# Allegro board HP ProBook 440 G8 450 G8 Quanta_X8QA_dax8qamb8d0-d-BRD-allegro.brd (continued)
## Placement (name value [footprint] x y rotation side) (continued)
PR9816  *Short_0201  [S0201]  38.33 104.42 180 top
PR9817  20K_1%_2  [R0201]  36.85 106.63 270 top
PR9819  4.7_5%_4  [R0402]  38.53 102.36 0 top
PR9820  *Short_0201  [S0201]  31.29 103.43 270 top
PR9821  10K_1%_2  [R0201]  30.58 103.43 270 top
PR9822  1K_1%_2  [R0201]  37.39 101.52 180 top
PR9823  1K_1%_2  [R0201]  37.39 100.81 180 top
PR9825  22_5%_8  [R0805]  59.38 94.82 0 bottom
PR9826  100K_1%_2  [R0201]  55.95 95.83 0 bottom
PR9827  1M_5%_2  [R0201]  54.91 95.83 0 bottom
PR9828  10K_1%_2  [R0201]  38.33 105.86 180 top
PR9829  *100K_1%_2  [R0201]  38.35 104.04 180 bottom
PR9830  *Short_0201  [S0201]  41.98 100.53 90 bottom
PR9831  *0_5%_2  [R0201]  41.1 100.4 0 bottom
PR9832  *0_5%_2  [R0201]  39.39 99.97 0 bottom
PR9833  *20K_1%_2  [R0201]  33.63 102.77 270 bottom
PR9900  *Short_0201  [S0201]  60.09 101.01 90 top
PR9901  *2.2_5%_6  [R0603]  74.14 105.74 0 bottom
PR9902  *2.2_5%_6  [R0603]  57.22 99.39 90 bottom
PR10200  113K_1%_4  [R0402]  31.19 93.01 90 bottom
PR10201  5.1_5%_6  [R0603]  26.64 89.05 90 top
PR10202  *Short_0805  [S0805]  29.67 79.32 180 top
PR10203  1_5%_6  [R0603]  25.02 87.45 270 bottom
PR10204  *Short_0402  [S0402]  27.02 93.01 270 bottom
PR10205  *10K_1%_2  [R0201]  28.88 93.01 270 bottom
PR10206  *2.2_5%_6  [R0603]  32.18 82.32 90 bottom
PR10207  10K_1%_2  [R0201]  28.27 91.18 90 top
PR10208  *Short_0402  [S0402]  28.01 93.01 270 bottom
PR10209  *Short_0402  [S0402]  24.53 80.06 0 top
PR10210  15K_1%_2  [R0201]  29.61 93.01 90 bottom
PR10211  12K_1%_2  [R0201]  30.35 93.01 90 bottom
PR10212  *100K_1%_4  [R0402]  21.9 63.55 270 top
PR10213  *22_5%_8  [R0805]  28.14 62.56 0 top
PR10214  *1M_4  [R0402]  22.87 65.86 0 top
PR10215  *Short_0805  [S0805]  31.7 81.35 180 top
PR10501  10K_1%_2  [R0201]  70.79 58.34 180 bottom
PR10502  *Short_0603  [S0603]  57.92 60.12 0 bottom
PR10503  *Short_0402  [S0402]  70.79 59.56 270 bottom
PR10504  22_5%_8  [R0805]  56.26 57.72 90 bottom
PR10505  *Short_0201  [S0201]  61.42 57.41 90 bottom
PR10506  *Short_0201  [S0201]  65.5 61.08 270 bottom
PR10507  100K_1%_2  [R0201]  50.24 57.1 90 bottom
PR10508  *0_5%_2  [R0201]  66.24 61.08 270 bottom
PR10509  1M_1%_2  [R0201]  50.11 58.24 90 bottom
PR10510  6.65K_1%_4  [R0402]  73.55 57.58 180 bottom
PR10511  10K_1%_2  [R0201]  69.42 56.38 0 bottom
PR10512  *Short_0603  [S0603]  90.5 70.18 90 top
PR10514  *Short_0603  [S0603]  84.86 71.32 0 top
PR10515  *Short_0603  [S0603]  84.98 77.7 180 top
PR10516  *Short_0201  [S0201]  92.05 77.37 90 top
PR10517  *Short_0201  [S0201]  91.76 71.63 180 top
PR10518  100K_1%_2  [R0201]  71.91 99.31 180 top
PR10519  22_5%_8  [R0805]  69.34 97.13 0 top
PR10520  1M_1%_2  [R0201]  71.68 98.45 270 top
PR10611  *Short_0603  [S0603]  136.04 92.61 180 top
PR10612  *Short_0201  [S0201]  135.19 97.64 90 top
PR10613  *0_5%_2  [R0201]  134.92 93.72 180 top
PR10614  *Short_0201  [S0201]  134.92 94.46 180 top
PR10615  *Short_0603  [S0603]  136.25 96.57 90 top
PR10617  100K_1%_4  [R0402]  158.82 82.01 0 bottom
PR10618  100K_1%_4  [R0402]  157 76.17 270 bottom
PR10619  100K_1%_2  [R0201]  158.58 77.03 0 bottom
PR10621  *Short_0201  [S0201]  158.32 76.25 180 bottom
PR10622  *Short_0201  [S0201]  157.91 75.31 90 bottom
PR10623  *0_5%_2  [R0201]  134.95 99.39 90 bottom
PR10625  10K_1%_2  [R0201]  119.63 13.33 270 bottom
PU8100  AS393MTR-G1  [SOIC8-6-1_27-24AA02]  39.96 15.53 270 bottom
PU8101  G1363U61U  [DFN6-1_6X1_6-5-7P-0_6H]  177.85 14.12 0 top
PU8102  MC74VHC1G08DFT2G  [SOT353-2_1-65-5P]  188.64 12.32 180 bottom
PU8200  BQ24780SRUYR  [QFN28-4X4-4-29P-BQ24780RUYR]  57.48 6.3 180 top
PU8201  G753T11U  [SOT23-5-2_8-95-5P-G708]  61.92 3.76 180 bottom
PU8601  SYV127FTMC  [QFN13-4X3-45]  167.28 13.46 0 bottom
PU8602  NB680AGD-Z  [QFN12-2X3-5]  142.45 16.13 90 bottom
PU8700  RT8231BGQW  [QFN20-3X3-4-21P-RT6543B]  104.33 11.52 0 top
PU8701  G2822CTB1U  [SOT23-2_8-95-6P-G2822C]  180.82 16.61 0 bottom
PU8800  ISL95860HRTZ-T  [QFN32-4X4-4-33P-ISL95860]  85.27 106.93 0 top
PU8900  SIC536CD-T1-GE3  [POWER-4_5X3_5-5-13P]  94.26 106.1 0 bottom
PU8901  SIC536CD-T1-GE3  [POWER-4_5X3_5-5-13P]  106.54 106.45 0 bottom
PU9100  MP2941BGL-Z  [QFN19-4X3-4]  115.14 106.88 0 bottom
PU9200  NB691GG-Z  [QFN11-2X2-5]  122.14 15.57 90 bottom
PU9500  G2898  [DFN14-3X2-4-11P]  156.31 11.43 180 top
PU9501  G2898  [DFN14-3X2-4-11P]  25.12 11.19 0 top
PU9502  G2898  [DFN14-3X2-4-11P]  175.99 68.46 0 top
PU9600  *74LVC1G32GW  [SOT353-2_1-65-5P-1_1H]  145.13 94.38 270 bottom
PU9601  *74LVC1G32GW  [SOT353-2_1-65-5P-1_1H]  148.74 103.07 180 top
PU9800  MP2988GQ  [QFN20-3X3-4-21P-MP2988]  35.08 103.5 180 top
PU9900  MP86948GQVT-Z  [QFN21-5X3-4-15P]  75.79 108.66 180 bottom
PU9901  MP86948GQVT-Z  [QFN21-5X3-4-15P]  54.3 101.29 270 bottom
PU10200  AOZ2264QI-20  [QFN23-4X4-5-20P]  29 88.39 0 bottom
PU10500  G2822CTB1U  [SOT23-2_8-95-6P-G2822C]  67.79 58.34 180 bottom
PU10501  G2894  [DFN14-3X2-4-11P]  88.16 73.86 90 top
PU10601  G2894  [DFN14-3X2-4-11P]  132.69 94.97 90 top
PU10602  *74LVC1G32GW  [SOT353-2_1-65-5P-1_1H]  145.01 97.69 0 top
PU10603  *74LVC1G32GW  [SOT353-2_1-65-5P-1_1H]  163.09 87.8 0 top
PU10604  *74LVC1G32GW  [SOT353-2_1-65-5P-1_1H]  144.93 103.07 180 top
PU10605  *74LVC1G32GW  [SOT353-2_1-65-5P-1_1H]  160.18 85.89 90 top
PU10606  *74LVC1G32GW  [SOT353-2_1-65-5P-1_1H]  125.7 105.46 270 top
Q500  2N7002K  [SOT23-2-95-3P]  91.13 67.66 0 bottom
Q501  METR3904-G  [SOT23-2-95-3P]  94.59 68.86 270 bottom
Q800  PJE138K  [SOT23-1_38-5-3P]  157.07 51.51 180 top
Q801  PJE138K  [SOT23-1_38-5-3P]  158.33 49.27 180 top
Q1000  *PJE138K  [SOT23-1_38-5-3P]  91.67 64.59 270 bottom
Q1100  2N7002KDW  [SOT363-2_1-65-6P]  152.37 76.92 180 bottom
Q1400  2N7002K  [SOT23-2-95-3P]  159.02 63.8 0 top
Q1500  2N7002K  [SOT23-2-95-3P]  148.94 46.43 270 top
Q1501  BSS84  [SOT23-2-95-3P]  154.9 39.89 270 top
Q1502  BSS84  [SOT23-2-95-3P]  153.89 43.8 0 top
Q3403  PJE138K  [SOT23-1_38-5-3P]  23.95 47.44 180 top
Q3404  PJE138K  [SOT23-1_38-5-3P]  21.26 48.16 180 top
Q3405  PJE138K  [SOT23-1_38-5-3P]  35.4 34.52 180 top
Q3406  PJE138K  [SOT23-1_38-5-3P]  28.62 23.8 0 top
Q3600  *METR3904-G  [SOT23-2-95-3P]  184.55 45.93 180 top
Q4104  2N7002K  [SOT23-2-95-3P]  183.49 68.35 270 top
Q4106  2N7002K  [SOT23-2-95-3P]  184.91 86.28 180 top
Q4108  METR3904-G  [SOT23-2-95-3P]  192.02 69.85 270 top
Q4111  METR3904-G  [SOT23-2-95-3P]  195.86 69.39 0 top
Q4112  *2N7002K  [SOT23-2-95-3P]  188.49 68.84 90 top
Q4200  2N7002K  [SOT23-2-95-3P]  197.1 7.72 90 top
Q4300  *PJE138K  [SOT23-2-95-3P]  18.36 51.74 270 top
Q4400  2N7002KDW  [SOT363-2_1-65-6P]  187.47 33.27 180 top
Q4401  *PJE138K  [SOT23-1_38-5-3P]  146.2 50.62 180 top
Q4703  2N7002KDW  [SOT363-2_1-65-6P]  186.74 9.37 180 top
Q4800  2N7002K  [SOT23-2-95-3P]  202.79 12.19 0 bottom
Q5000  *2N7002KDW  [SOT363-2_1-65-6P]  179.19 62.15 270 top
Q5001  PJE138K  [SOT23-1_38-5-3P]  170.51 32.2 180 top
Q5004  PJE138K  [SOT23-1_38-5-3P]  169.62 34.41 0 top
Q5005  AO3409  [SOT23-2_38-95-3P]  46.14 9.7 180 bottom
Q5006  2N7002K  [SOT23-2-95-3P]  45.88 13.35 180 bottom
Q5101  *DMN2990UDJ-7  [SOT963-1-35-6P-SMT]  168.48 66.11 90 top
Q5201  *PJE138K  [SOT23-1_38-5-3P]  26.69 5.66 0 top
Q5202  *PJE138K  [SOT23-1_38-5-3P]  35.56 9.57 90 top
Q5401  2N7002KDW  [SOT363-2_1-65-6P]  35.33 57.45 180 bottom
Q5403  METR3904-G  [SOT23-2-95-3P]  73.33 45.74 90 top
Q5404  2N7002KDW  [SOT363-2_1-65-6P]  90.66 70.65 0 bottom
Q6100  *PJA138K  [SOT23-2-95-3P]  196.9 69.21 0 bottom
Q6600  LTC044EUBFS8TL  [SOT23-1_7-65-3P]  83.01 64.87 180 bottom
Q6601  LTC044EUBFS8TL  [SOT23-1_7-65-3P]  82.57 62.25 180 bottom
Q6800  METR3904-G  [SOT23-2-95-3P]  46.33 57.94 270 bottom
Q6801  LTC044EUBFS8TL  [SOT23-1_7-65-3P]  59.36 92.4 0 bottom
Q6802  *METR3904-G  [SOT23-2-95-3P]  39.77 58.27 180 bottom
Q6900  PJT138K  [SOT363-2_1-65-6P-PJ4N3KDW]  77.41 94.54 180 bottom
Q6901  DMN5L06DWK-7  [SOT363-2_1-65-6P-DMC2004DWK-7]  83.5 70.85 90 bottom
Q6902  PJE138K  [SOT23-1_38-5-3P]  85.34 61.9 180 bottom
Q6903  DMN5L06DWK-7  [SOT363-2_1-65-6P-DMC2004DWK-7]  87.58 82.24 90 bottom
Q6904  PJE138K  [SOT23-1_38-5-3P]  87.45 78.92 270 bottom
Q7000  2N7002K  [SOT23-2-95-3P]  29.61 97.41 90 top
Q7001  2N7002K  [SOT23-2-95-3P]  29.16 70.46 270 bottom
Q7500  *PJE138K  [SOT23-1_38-5-3P]  22.15 37.21 90 top
Q7502  PJE138K  [SOT23-1_38-5-3P]  17.78 48.61 90 top
Q7506  *2N7002KTB  [SOT23-1_38-5-3P]  12.6 38.68 0 top
Q7507  PJE138K  [SOT23-1_38-5-3P]  22.32 34.74 180 top
Q7508  PJE138K  [SOT23-1_38-5-3P]  19.73 36.37 0 top
Q7600  2N7002K  [SOT23-2-95-3P]  179.34 47.35 90 top
R400  150_1%_2  [R0201]  114.58 89.53 90 bottom
R401  100K_5%_2  [R0201]  149.12 83.62 0 bottom
R402  150_1%_2  [R0201]  111.61 89.38 0 bottom
R403  100K_1%_2  [R0201]  103.75 90.03 90 top
R404  100K_2  [R0201]  143.66 55.93 0 top
R405  *100K_2  [R0201]  155.92 65.08 0 top
R406  *10K_5%_2  [R0201]  143.66 59.06 90 bottom
R407  *10K_5%_2  [R0201]  143.89 57.82 270 top
R500  100_1%_2  [R0201]  97.69 64.16 90 bottom
R504  10K_5%_2  [R0201]  89.09 67.71 270 bottom
R506  10K_5%_2  [R0201]  92.86 70.42 0 bottom
R509  470_1%_2  [R0201]  152.88 54.31 90 top
R510  0_5%_2  [R0201]  153.64 54.31 270 top
R511  *100K_5%_2  [R0201]  88.95 66.83 0 bottom
R512  10K_5%_2  [R0201]  95.78 65.81 90 bottom
R513  100K_5%_2  [R0201]  95.25 66.7 0 bottom
R600  1K_1%_2  [R0201]  106.55 80.66 270 top
R602  1K_1%_2  [R0201]  92.66 83.51 0 bottom
R603  499_1%_2  [R0201]  99.97 90.53 270 bottom
R604  1K_1%_2  [R0201]  108.29 80.94 270 top
R605  *51_1%_2  [R0201]  94.16 82.62 180 bottom
R606  49.9_1%_2  [R0201]  134.54 71.19 270 top
R607  100_1%_2  [R0201]  96.14 74.24 180 bottom
R608  49.9_1%_2  [R0201]  127.99 81.53 180 top
R609  *0_5%_2/S  [S0201]  93.42 84.4 180 bottom
R610  *51_1%_2  [R0201]  96.28 76.94 270 bottom
R611  *0_5%_2/S  [S0201]  95.3 82.62 0 bottom
R612  *0_5%_2/S  [S0201]  97.56 73.46 0 bottom
R613  *0_5%_2/S  [S0201]  97.72 76.69 270 bottom
R614  *51_1%_2  [R0201]  94.94 81.23 180 bottom
R615  *0_5%_2/S  [S0201]  104.14 90.6 270 bottom
R616  100_1%_2  [R0201]  96.14 74.95 180 bottom
R617  51_1%_2  [R0201]  94.94 84.4 0 bottom
R618  *51_1%_2  [R0201]  101.14 90.64 90 bottom
R620  *51_1%_2  [R0201]  94.94 83.64 180 bottom
R621  1K_1%_2  [R0201]  92.66 82.62 180 bottom
R624  *1K_1%_2  [R0201]  102.16 90.64 270 bottom
R625  10K_5%_2  [R0201]  152.27 81.48 270 top
R626  200K_2  [R0201]  46.23 7.52 0 bottom
R627  100K_1%_2  [R0201]  138.05 58.47 180 top
R628  100K_2  [R0201]  146.8 90.22 0 bottom
R700  *0_5%_4/S  [S0402]  96.27 75.96 0 bottom
R703  56_1%_2  [R0201]  101.8 93.19 90 top
R704  100_1%_2  [R0201]  100.81 93.47 90 top
R705  *0_5%_2/S  [S0201]  101.8 91.44 90 top
R706  *0_5%_2/S  [S0201]  102.82 91.44 90 top
R707  *0_5%_2/S  [S0201]  100.84 92.07 90 top
R800  200_1%_2  [R0201]  145.08 57.45 270 top
R801  *10K_5%_2  [R0201]  137.84 59.48 90 bottom
R802  100K/F_2  [R0201]  136.42 59.48 270 bottom
R803  100K/F_2  [R0201]  157.94 72.64 270 bottom
R804  10K_5%_2  [R0201]  135.61 59.48 270 bottom
R805  2.2K_5%_2  [R0201]  148.89 78.71 90 bottom
R806  2.2K_5%_2  [R0201]  149.6 78.36 90 bottom
R807  *100K/F_2  [R0201]  149.48 73.72 0 bottom
R810  *10K_5%_2  [R0201]  138.1 58.44 270 bottom
R811  100K/F_2  [R0201]  136.75 58.16 180 top
R812  100K/F_2  [R0201]  179.78 87.76 0 top
R813  100K/F_2  [R0201]  151.33 74.9 0 top
R814  10K_5%_2  [R0201]  154.49 74.95 180 top
R815  *2.2K_2  [R0201]  136.78 60.35 0 top
R816  *2.2K_2  [R0201]  136.78 59.56 0 top
R817  100K/F_2  [R0201]  193.51 6.42 270 top
R818  0_5%_2  [R0201]  155.67 53.16 90 top
R819  47K_1%_2  [R0201]  157.38 54.38 270 top
R820  1M_5%_2  [R0201]  138.53 75.51 180 top
R1000  49.9_1%_2  [R0201]  94.94 85.16 0 bottom
R1001  2.2K_5%_2  [R0201]  115.36 89.53 270 bottom
R1002  *1K_5%_2  [R0201]  97.26 72.5 180 top
R1003  *1K_5%_2  [R0201]  108.62 78.76 0 top
R1004  *10K_5%_2  [R0201]  93.24 65.15 90 bottom
R1005  *10K_5%_2  [R0201]  90.17 65.35 90 bottom
R1006  *1K_5%_2  [R0201]  107.58 78.76 0 top
R1007  *0_5%_2  [R0201]  94.1 65.15 270 bottom
R1008  *10K_5%_2  [R0201]  93.55 63.9 180 bottom
R1009  *1K_5%_2  [R0201]  96.23 74.04 90 top
R1010  *1K_5%_2  [R0201]  96.36 72.45 270 top
R1011  *1K_5%_2  [R0201]  107.28 80.86 90 top
R1012  *1K_5%_2  [R0201]  92.25 73.76 180 bottom
R1013  *1K_5%_2  [R0201]  93.65 75.13 0 bottom
R1014  *1K_5%_2  [R0201]  93.65 76.63 0 bottom
R1015  *1K_5%_2  [R0201]  93.67 74.37 0 bottom
R1016  *1K_5%_2  [R0201]  93.65 75.89 0 bottom
R1017  *1K_5%_2  [R0201]  93.65 72.84 0 bottom
R1018  *1K_5%_2  [R0201]  93.65 71.35 0 bottom
R1019  *1K_5%_2  [R0201]  93.65 73.61 0 bottom
R1020  *1K_5%_2  [R0201]  93.65 72.08 0 bottom
R1021  *1K_5%_2  [R0201]  95.35 70.63 90 top
R1022  *1K_5%_2  [R0201]  97.45 73.66 0 top
R1023  *1K_5%_2  [R0201]  93.71 72.4 0 top
R1024  *1K_5%_2  [R0201]  93.71 71.64 0 top
R1025  *1K_5%_2  [R0201]  94.57 70.63 90 top
R1026  *1K_5%_2  [R0201]  96.88 70.63 90 top
R1027  *1K_5%_2  [R0201]  97.61 70.64 90 top
R1028  1K_5%_2  [R0201]  92.5 76.45 270 bottom
R1029  *1K_5%_2  [R0201]  96.13 70.64 90 top
R1030  *1K_5%_2  [R0201]  91.9 74.67 180 bottom
R1031  *1K_5%_2  [R0201]  97.56 83.39 180 bottom
R1032  *10K_1%_2  [R0201]  109.34 89.89 270 top
R1033  *10K_1%_2  [R0201]  110.82 89.89 270 top
R1034  1K_5%_2  [R0201]  96 75.62 0 top
R1035  *10K_1%_2  [R0201]  108.61 89.89 270 top
R1036  *10K_1%_2  [R0201]  110.08 89.89 270 top
R1037  *51_1%_2  [R0201]  96.89 72.32 0 bottom
R1038  *1K_5%_2  [R0201]  94.14 74.92 180 top
R1039  *1K_5%_2  [R0201]  97.56 82.67 180 bottom
R1040  *1K_5%_2  [R0201]  93.92 75.8 270 top
R1041  *1K_5%_2  [R0201]  94.08 74.07 180 top
R1042  *1K_5%_2  [R0201]  96.03 74.9 0 top
R1043  *1K_5%_2  [R0201]  95.08 73.84 0 top
R1100  4.7_5%_2  [R0201]  160.73 72.84 0 top
R1101  4.7_5%_2  [R0201]  150.82 71.42 0 top
R1102  *0_5%_2/S  [S0201]  150.32 68.07 0 top
R1103  4.7_5%_2  [R0201]  149.83 70.84 0 top
R1104  4.7_5%_2  [R0201]  148.38 70.79 0 top
R1105  4.7_5%_2  [R0201]  148.26 69.01 0 top
R1106  *0_5%_2/S  [S0201]  156.31 76.3 0 top
R1107  *0_5%_2/S  [S0201]  156.31 77.09 0 top
R1108  49.9_1%_2  [R0201]  148.16 60.09 0 bottom
R1109  15_1%_2  [R0201]  144.52 59.11 0 bottom
R1110  15_1%_2  [R0201]  145.51 59.11 180 bottom
R1111  15_1%_2  [R0201]  148.16 60.8 0 bottom
R1112  15_1%_2  [R0201]  148 61.68 90 bottom
R1114  2.2K_5%_2  [R0201]  151.33 74.9 180 bottom
R1115  *0_5%_2/S  [S0201]  146.55 59.19 180 bottom
R1116  2.2K_5%_2  [R0201]  153.79 78.81 0 bottom
R1117  *0_5%_2/S  [S0201]  140.16 58.95 270 top
R1119  100K_5%_2  [R0201]  151.53 81.48 90 top
R1120  1M/F_2  [R0201]  153.26 10.37 90 bottom
R1121  *10K_5%_2  [R0201]  140.43 89.38 270 top
R1122  *75K_1%_2  [R0201]  146.55 58.47 0 bottom
R1123  100K_5%_2  [R0201]  139.42 58.95 270 top
R1124  10K_5%_2  [R0201]  150.06 80.59 0 bottom
R1125  2.2K_5%_2  [R0201]  153.62 74.88 0 bottom
R1126  2.2K_5%_2  [R0201]  151.92 78.84 90 bottom
R1127  10K_5%_2  [R0201]  149.05 80.59 180 bottom
R1128  499_1%_2  [R0201]  152.3 72.97 180 top
R1129  499_1%_2  [R0201]  151.9 78.84 90 top
R1130  2.2K_5%_2  [R0201]  157.22 76.02 90 top
R1131  2.2K_5%_2  [R0201]  157.22 77.01 270 top
R1132  100K_1%_2  [R0201]  188.64 5.64 0 top
R1133  *0_5%_2  [R0201]  152.8 78.81 0 bottom
R1134  100K/F_2  [R0201]  150.06 80.16 180 top
R1135  100K_2  [R0201]  149.05 80.16 180 top
R1136  100K_2  [R0201]  150.06 81.4 180 bottom
R1137  100K_2  [R0201]  149.05 81.4 180 bottom
R1138  100K_2  [R0201]  150.06 79.42 180 top
R1139  *100K/F_2  [R0201]  149.05 79.42 180 top
R1140  *0_5%_2  [R0201]  152.47 74.9 180 bottom
R1141  100K/F_2  [R0201]  149.05 78.66 180 top
R1142  100K_2  [R0201]  148.08 78.46 270 top
R1143  *10K_5%_2  [R0201]  150.06 79.6 180 bottom
R1144  *10K_5%_2  [R0201]  149.05 79.6 180 bottom
R1145  10K_5%_2  [R0201]  151.18 81.4 180 bottom
R1146  10K_5%_2  [R0201]  80.54 102.54 0 bottom
R1200  *4.7K_5%_2  [R0201]  140.08 58.27 0 bottom
R1201  *100K_5%_2  [R0201]  148.12 72.59 90 top
R1202  100K_5%_2  [R0201]  149.86 73.02 90 top
R1203  100K_5%_2  [R0201]  148.99 72.36 0 top
R1204  *100K_5%_2  [R0201]  150.01 72.16 0 top
R1205  *100K_5%_2  [R0201]  148.12 73.58 270 top
R1206  100K_5%_2  [R0201]  148.99 73.08 0 top
R1207  *4.7K_5%_2  [R0201]  156.54 82.34 180 top
R1208  *4.7K_5%_2  [R0201]  150.09 77.92 180 top
R1209  *4.7K_5%_2  [R0201]  150.42 75.72 180 top
R1210  *4.7K_5%_2  [R0201]  150.42 76.45 180 top
R1211  100K_5%_2  [R0201]  148.99 73.81 0 top
R1212  *100K_5%_2  [R0201]  149.98 73.89 0 top
R1213  *20K_1%_2  [R0201]  140.03 59.15 270 bottom
R1214  *4.7K_5%_2  [R0201]  150.85 65.38 0 bottom
R1215  *20K_1%_2  [R0201]  155.52 82.34 180 top
R1216  *20K_1%_2  [R0201]  149.05 77.92 180 top
R1217  *20K_1%_2  [R0201]  148.84 75.99 90 top
R1218  *20K_1%_2  [R0201]  149.55 76.32 270 top
R1219  *20K_1%_2  [R0201]  150.85 66.14 180 bottom
R1220  *4.7K_5%_2  [R0201]  138.1 59.36 90 top
R1221  100K_5%_2  [R0201]  151.43 72.67 90 top
R1222  *100K_5%_2  [R0201]  152.74 78.86 180 top
R1223  *4.7K_5%_2  [R0201]  137.34 58.47 90 bottom
R1224  *4.7K_5%_2  [R0201]  155.51 72.87 180 top
R1225  *4.7K_5%_2  [R0201]  153.59 78.69 270 top
R1226  4.7K_5%_2  [R0201]  152.7 76.38 0 top
R1227  *4.7K_5%_2  [R0201]  140.66 77.04 0 top
R1228  *20K_1%_2  [R0201]  137.13 59.48 270 bottom
R1229  *20K_1%_2  [R0201]  153.64 75.61 270 top
R1230  *100K_5%_2  [R0201]  152.98 82.42 270 top
R1231  100K_5%_2  [R0201]  153.74 82.42 270 top
R1232  *4.7K_5%_2  [R0201]  188.42 39.62 270 top
R1233  *4.7K_5%_2  [R0201]  154.51 82.42 270 top
R1234  *4.7K_5%_2  [R0201]  140.61 79.02 90 top
R1235  20K_1%_2  [R0201]  139.75 79.25 180 top
R1236  4.7K_5%_2  [R0201]  160.45 73.79 270 top
R1237  1M_5%_2  [R0201]  157.17 66.47 90 top
R1238  1K_5%_2  [R0201]  159.74 73.67 90 top
R1239  *4.7K_5%_2  [R0201]  162 74.8 0 top
R1240  *10K_1%_2  [R0201]  157.07 67.49 90 top
R1241  *4.7K_5%_2  [R0201]  137.28 78.59 90 top
R1242  1K_5%_2  [R0201]  140.03 92.78 90 bottom
R1243  *20K_1%_2  [R0201]  136.55 78.59 270 top
R1244  *1K_5%_2  [R0201]  140.13 91.74 270 bottom
R1245  100K_1%_2  [R0201]  153.77 68.02 90 top
R1246  *1K_5%_2  [R0201]  154.51 68.53 270 top
R1247  *4.7K_5%_2  [R0201]  149.87 65.33 180 bottom
R1248  *4.7K_5%_2  [R0201]  162.61 71.57 270 top
R1249  4.7K_5%_2  [R0201]  148.71 63.65 0 bottom
R1300  100_1%_2  [R0201]  148.08 83.06 90 bottom
R1301  10K_5%_2  [R0201]  136.34 80.85 0 top
R1302  10K_5%_2  [R0201]  139.9 89.71 270 bottom
R1303  113_1%_2  [R0201]  139.16 89.79 90 bottom
R1304  2.2K_5%_2  [R0201]  109.5 79.5 0 top
R1306  *10K_5%_2  [R0201]  142.59 58.62 180 top
R1307  100K_5%_2  [R0201]  154.33 80.49 270 top
R1308  100K_5%_2  [R0201]  154.89 48.49 90 top
R1400  *20K_1%_2  [R0201]  153.59 80.46 270 top
R1401  *20K_1%_2  [R0201]  152.86 80.46 270 top
R1402  10K_5%_2  [R0201]  149.05 76.02 0 bottom
R1403  10K_5%_2  [R0201]  149.48 72.3 0 bottom
R1404  10K_5%_2  [R0201]  154.31 72.27 180 top
R1405  150_1%_2  [R0201]  147.46 59.21 270 bottom
R1406  10K_5%_2  [R0201]  151.2 71.32 90 bottom
R1407  100K_1%_2  [R0201]  148.79 75 90 top
R1408  10K_5%_2  [R0201]  149.48 73.01 0 bottom
R1409  *0_5%_2/S  [S0201]  154.71 79.12 90 top
R1410  *0_5%_2/S  [S0201]  135.81 78.05 270 top
R1411  10K_5%_2  [R0201]  179.35 44.59 270 top
R1412  75K_1%_2  [R0201]  147.83 90.22 180 bottom
R1413  *10K_5%_2  [R0201]  139.04 74.42 270 top
R1414  10K_5%_2  [R0201]  150.34 74.95 0 top
R1415  *0_2/S  [S0201]  160.86 70.15 90 top
R1416  20K_1%_2  [R0201]  156.28 67.56 90 top
R1417  150_1%_2  [R0201]  96.91 70.89 0 bottom
R1418  20K_1%_2  [R0201]  156.44 65.97 270 top
R1419  1K_1%_2  [R0201]  172.29 6.9 90 top
R1420  10M_2  [R0201]  173.07 5.79 270 top
R1421  *0_5%_2  [R0201]  155.57 67.56 270 top
R1422  60.4_1%_2  [R0201]  139.65 89.38 270 top
R1423  *0_5%_2/S  [S0201]  148.59 54.99 180 top
R1424  0_5%_2  [R0201]  141.7 89.74 270 bottom
R1425  10M_5%_2  [R0201]  149.5 53.62 90 top
R1426  200K_1%_2  [R0201]  142.06 91.67 0 bottom
R1427  *0_5%_2/S  [S0201]  150.37 53.24 270 top
R1428  *0_5%_2/S  [S0201]  149.58 54.99 0 top
R1429  0_5%_2  [R0201]  142.64 89.76 270 bottom
R1500  33_5%_2  [R0201]  148.18 68.88 0 bottom
R1501  33/F_2  [R0201]  142.16 56.35 90 top
R1502  33_5%_2  [R0201]  148.11 69.59 0 bottom
R1503  33_5%_2  [R0201]  148.11 66.98 0 bottom
R1504  200_1%_2  [R0201]  138.68 73.23 90 top
R1505  *0_5%_2  [R0201]  139.95 68.27 0 top
R1506  *0_5%_2  [R0201]  144.43 54.87 0 top
R1507  *100K_1%_2  [R0201]  152.3 72.26 180 top
R1509  *0_5%_2  [R0201]  153.64 41.58 0 top
R1510  10K_5%_2  [R0201]  195.12 88.82 270 bottom
R1511  100K_5%_2  [R0201]  148.61 68.04 270 bottom
R1512  200K_1%_2  [R0201]  151.05 67.76 270 bottom
R1513  *0_5%_2/S  [S0201]  161.44 67.61 270 top
R1514  100K_5%_2  [R0201]  149.32 68.04 270 bottom
R1515  8.2K_1%_2  [R0201]  154.13 66.09 0 top
R1516  *100K_5%_2  [R0201]  151.05 69.37 180 bottom
R1517  *100K_5%_2  [R0201]  150.68 70.08 180 bottom
R1518  *100K_5%_2  [R0201]  150.06 71.4 180 bottom
R1519  *100K_5%_2  [R0201]  149.83 70.53 270 bottom
R1520  100K_1%_2  [R0201]  189.3 8.58 0 top
R1521  100K_5%_2  [R0201]  137.13 67.46 180 top
R1522  *100K_5%_2  [R0201]  136.14 67.82 180 top
R1523  *100K_5%_2  [R0201]  154.28 72.98 0 top
R1524  *100K_5%_2  [R0201]  150.34 73.2 90 bottom
R1525  10K_5%_2  [R0201]  153.29 72.27 180 top
R1526  10K_5%_2  [R0201]  150.75 81.13 90 top
R1527  *0_5%_2/S  [S0201]  162.99 69.06 90 top
R1528  1M_5%_2  [R0201]  162.81 70.08 90 top
R1529  *100K_5%_2  [R0201]  162.08 69.49 90 top
R1530  10K_5%_2  [R0201]  148.82 44.14 0 top
R1531  10K_5%_2  [R0201]  152.96 66.93 270 top
R1532  8.2K_1%_2  [R0201]  151.71 67.11 0 top
R1533  100K_5%_2  [R0201]  159.46 70.81 180 bottom
R1534  100K_1%_2  [R0201]  143.7 56.78 180 top
R1535  *8.2K_1%_2  [R0201]  152.91 67.8 0 top
R1536  *0_2/S  [S0201]  151.79 45.11 180 top
R1537  100K_5%_2  [R0201]  14.22 38.78 270 top
R1538  *10K_5%_2  [R0201]  142.59 57.88 180 top
R1539  *33.2K_1%_2  [R0201]  149.86 66.62 180 bottom
R1540  *100K_5%_2  [R0201]  22.78 7.52 270 top
R1541  100K_5%_2  [R0201]  19.31 41.33 90 top
R1542  100K_5%_2  [R0201]  144.69 56.18 0 top
R1543  33_1%_2  [R0201]  187.7 39.62 90 top
R1544  100K_5%_2  [R0201]  148.71 64.36 180 bottom
R1545  *100K_5%_2  [R0201]  28.83 31.13 270 top
R1546  *100K_5%_2  [R0201]  140.89 58.98 90 top
R1548  100K_5%_2  [R0201]  148.13 77.34 270 bottom
R1549  *10K_5%_2  [R0201]  122.71 81.53 0 top
R1550  0_5%_2  [R0201]  160.48 70.81 180 bottom
R1553  4.7K_2  [R0201]  149.79 80.96 0 top
R1560  1K_1%_2  [R0201]  156.08 41.63 180 top
R1561  1K_1%_2  [R0201]  125.24 81.4 270 top
R1562  *100K_1%_2  [R0201]  161.16 72.34 90 bottom
R1566  60.4_1%_2  [R0201]  124.25 81.39 90 top
R1572  *0_5%_2  [R0201]  157.94 73.66 270 bottom
R1573  *0_5%_2  [R0201]  150.04 68.04 270 bottom
R1574  *100K_5%_2  [R0201]  161.67 68.48 0 top
R1575  *100K_1%_2  [R0201]  151.05 68.65 0 bottom
R1576  100K_1%_2  [R0201]  155.22 74.14 0 bottom
R1601  *0_5%_4/S  [S0402]  154.53 82.42 0 bottom
R1602  *1K_5%_2  [R0201]  138.46 79.45 90 top
R1603  *100K_1%_2  [R0201]  136.65 79.55 180 top
R1604  *0_5%_4/S  [S0402]  159.03 67.51 0 top
R1605  *0_5%_2/S  [S0201]  136.22 70.46 270 top
R1606  *0_5%_4/S  [S0402]  156.84 66.6 270 bottom
R1607  *0_5%_2/S  [S0201]  137.13 69.24 180 top
R1609  *0_5%_2  [R0201]  135.58 74.24 180 top
R1610  *0_5%_2/S  [S0201]  135.58 73.35 0 top
R1611  *100K_5%_2  [R0201]  136.14 69.24 0 top
R1612  *100K_5%_2  [R0201]  136.22 68.53 0 top
R1613  100K_5%_2  [R0201]  153.94 66.18 0 bottom
R1614  *0_5%_2  [R0201]  153.94 66.99 0 bottom
R1615  100_1%_2  [R0201]  153.79 69.49 0 bottom
R1616  *0.01_1%_6  [R0603]  154.86 68.43 180 bottom
R1617  1M_5%_2  [R0201]  135.43 72.03 270 top
R1900  0_5%_6  [R0603]  146.38 103.83 180 bottom
R1901  0_5%_4  [R0402]  148.28 103.58 90 bottom
R1902  0_5%_4  [R0402]  149.3 103.58 90 bottom
R1903  0_5%_4  [R0402]  151.33 103.58 90 bottom
R1904  0_5%_4  [R0402]  150.32 103.58 90 bottom
R2800  *0_6/S  [S0603]  158.8 20.62 0 top
R2801  240_2  [R0201]  149.83 22.4 270 top
R2802  *240_2  [R0201]  137.92 22.4 270 top
R2803  *240_2  [R0201]  138.71 25.52 270 top
R2804  *240_2  [R0201]  141.68 25.68 270 top
R2805  *240_2  [R0201]  143.2 26.74 90 top
R2806  *240_2  [R0201]  139.57 23.39 180 top
R2807  *240_2  [R0201]  138.71 26.59 90 top
R2808  *240_2  [R0201]  139.93 22.04 270 top
R2809  *240_2  [R0201]  142.82 21.74 270 top
R2810  240_2  [R0201]  139.67 26.59 90 top
R2811  1K_1%_2  [R0201]  157.5 21.87 90 top
R2812  *10K_5%_2  [R0201]  185.57 25.35 0 top
R2813  *10K_5%_2  [R0201]  185.65 24.48 90 top
R2814  *10K_5%_2  [R0201]  160.81 22.81 90 top
R2815  2/F_6  [R0603]  154.02 20.75 180 top
R2816  240_2  [R0201]  139.67 25.6 270 top
R2817  10K_5%_2  [R0201]  184.63 25.88 270 top
R2818  10K_5%_2  [R0201]  185.65 23.49 90 top
R2819  10K_5%_2  [R0201]  160.81 21.79 90 top
R2820  1K_1%_2  [R0201]  156.77 21.87 270 top
R2821  24.9/F_2  [R0201]  153.9 24.43 0 top
R2900  *0_6/S  [S0603]  110.67 21.03 180 top
R2901  240_2  [R0201]  73.91 21.74 90 top
R2902  *10K_5%_2  [R0201]  106.14 17.83 90 top
R2903  10K_5%_2  [R0201]  107.03 17.45 0 top
R2904  *10K_5%_2  [R0201]  83.97 21.79 270 top
R2905  10K_5%_2  [R0201]  105.43 17.83 270 top
R2906  *10K_5%_2  [R0201]  107.44 18.16 0 top
R2907  10K_5%_2  [R0201]  83.23 21.79 90 top
R2908  *240_2  [R0201]  61.44 21.89 270 top
R2909  *240_2  [R0201]  61.72 25.32 270 top
R2910  *240_2  [R0201]  63.22 24.89 90 top
R2911  *240_2  [R0201]  65.02 26.16 90 top
R2912  *240_2  [R0201]  61.44 23.04 90 top
R2913  *240_2  [R0201]  60.2 26.9 90 top
R2914  *240_2  [R0201]  63.45 21.77 270 top
R2915  *240_2  [R0201]  63.45 23.26 90 top
R2916  1K_1%_2  [R0201]  111.81 24.48 0 top
R2917  1K_1%_2  [R0201]  110.82 24.48 0 top
R2918  240_2  [R0201]  63.22 26.08 90 top
R2919  2/F_6  [R0603]  112.72 22.81 270 top
R2920  24.9/F_2  [R0201]  114.7 22.55 180 top
R2921  240_2  [R0201]  61.72 26.31 90 top
R3300  *100K/F_2  [R0201]  23.42 44.47 90 top
R3301  *10K_5%_2  [R0201]  22.6 45.67 180 top
R3302  10K/F_2  [R0201]  18.46 44.24 180 top
R3303  *10K/F_2  [R0201]  18.62 43.38 90 top
R3304  *0_2/S  [S0201]  18.31 45.49 270 top
R3305  *0_2/S  [S0201]  166.85 10.16 0 bottom
R3306  *0_2/S  [S0201]  139.22 13.03 180 bottom
R3307  *0_2/S  [S0201]  108.74 11.66 180 top
R3308  *0_2/S  [S0201]  119.56 12.44 180 bottom
R3309  *0_2/S  [S0201]  124.38 105.89 180 bottom
R3400  10K_5%_2  [R0201]  29.87 45.15 270 bottom
R3401  2.2K_2  [R0201]  31.82 39.03 270 bottom
R3402  2K_1%_2  [R0201]  24.71 49.35 90 top
R3403  2.2K_2  [R0201]  31.82 38.04 90 bottom
R3405  100K_1%_2  [R0201]  23.95 49.35 90 top
R3406  470K_2  [R0201]  30.07 39.92 180 bottom
R3407  47K_1%_2  [R0201]  21.65 50.58 270 top
R3408  *0_4/S  [S0402]  30.79 42.38 180 top
R3409  *0_2/S  [S0201]  19.56 48.84 90 top
R3410  *0_4/S  [S0402]  30.79 41.36 180 top
R3411  1K_1%_2  [R0201]  21.38 46.51 270 top
R3412  *0.01_1%_6/S  [S0603]  18.91 26.81 270 top
R3413  1K_1%_2  [R0201]  28.02 38.28 0 top
R3414  *100K_1%_2  [R0201]  31.06 32.13 180 bottom
R3415  *0.01_1%_6/S  [S0603]  27.51 30.17 90 top
R3417  *0_6/S  [S0603]  28.42 51.38 180 top
R3419  *0_6  [R0603]  30.45 52.02 270 top
R3420  *1K_2  [R0201]  192.2 13.71 180 bottom
R3421  *100K_2  [R0201]  31.45 33.53 90 top
R3422  *10K_5%_2  [R0201]  25.98 50.11 90 top
R3425  *1K_2  [R0201]  24.71 50.44 270 top
R3428  *0_5%_2  [R0201]  31.06 13.51 180 top
R3429  *100K_2  [R0201]  31.45 34.55 270 top
R3431  1M/F_2  [R0201]  29.57 38.08 0 top
R3432  *0_2/S  [S0201]  33.08 38.84 0 top
R3433  *0_2/S  [S0201]  33.07 39.84 0 top
R3434  1K_1%_2  [R0201]  26.1 40.34 90 top
R3435  *0_5%_2  [R0201]  28.78 25.8 180 top
R3500  150_5%_2  [R0201]  204.29 58.37 270 top
R3501  150_5%_2  [R0201]  204.29 56.33 270 top
R3502  150_5%_2  [R0201]  204.29 53.92 270 top
R3503  150_5%_2  [R0201]  204.29 52.02 270 top
R3504  *4.7K_2  [R0201]  200.51 51.2 270 top
R3505  *4.7K_2  [R0201]  200.51 52.22 90 top
R3506  *4.7K_2  [R0201]  200.45 52.3 180 bottom
R3507  *4.7K_2  [R0201]  199.62 51.2 270 top
R3508  *4.7K_2  [R0201]  199.62 52.22 90 top
R3509  2.2K_2  [R0201]  204.42 48.59 270 top
R3514  2.2K_2  [R0201]  204.41 49.67 90 top
R3515  4.02K_1%_4  [R0402]  201.34 52.42 90 top
R3516  2.2K_5%_2  [R0201]  199.44 62.05 180 top
R3517  2.2K_5%_2  [R0201]  199.18 61.31 180 top
R3600  2.2K_2  [R0201]  198.17 36.35 90 bottom
R3601  30/F_4  [R0402]  200.35 37.87 0 top
R3602  30/F_4  [R0402]  200 36.9 0 top
R3603  100K_2  [R0201]  201.58 34.35 90 top
R3604  *0.01_1%_6/S  [S0603]  199.31 31.77 90 top
R3605  *0_4/S  [S0402]  198.09 32.1 270 top
R3607  *0_8/S  [S0805]  195.53 36.01 270 bottom
R3608  100K_2  [R0201]  196.52 32.38 90 top
R3609  200K_2  [R0201]  194.93 33.32 180 top
R3610  100K_2  [R0201]  195.81 32.38 90 top
R3611  200K_2  [R0201]  190.88 39.01 90 bottom
R3612  1K_1%_2  [R0201]  188.54 35.53 270 top
R3613  1K_1%_2  [R0201]  189.69 34.36 270 top
R3614  33/F_2  [R0201]  190.17 36.77 0 top
R3616  *0_2/S  [S0201]  188 40.84 180 top
R3617  *0_2/S  [S0201]  188.14 38.63 0 top
R3618  *0_2/S  [S0201]  187.98 42.8 180 top
R3619  100K_2  [R0201]  191.84 41.48 90 top
R3620  *0_2  [R0201]  184.02 43.79 180 top
R3622  *10K/F_2  [R0201]  185.82 43.71 0 top
R3700  *0_4/S  [S0402]  198.65 33.73 0 bottom
R3701  BLM15BB121SN1D(120,300)  [R0402]  201.34 36.4 270 top
R3702  BLM15BB121SN1D(120,300)  [R0402]  202.13 37.87 0 top
R4101  *0.01_1%_6/S  [S0603]  197.57 77.35 270 top
R4102  10K_1%_2  [R0201]  199.71 71.85 180 top
R4112  75K/F_2  [R0201]  200.53 72.82 0 top
R4113  100K_1%_2  [R0201]  184.53 71.66 270 top
R4117  *0_2  [R0201]  183.23 70.89 180 top
R4118  10K_5%_2  [R0201]  185.16 82.4 180 top
R4119  *0_4/S  [S0402]  169.64 73.48 90 bottom
R4120  *0_4/S  [S0402]  168.68 73.48 90 bottom
R4121  4.7K_5%_2  [R0201]  173.43 81.13 0 bottom
R4126  49.9_1%_2  [R0201]  177.85 81.25 270 bottom
R4127  49.9_1%_2  [R0201]  180.46 81.28 270 bottom
R4128  *0_5%_2  [R0201]  181.86 81.25 270 bottom
R4129  *0_5%_2  [R0201]  182.7 81.25 270 bottom
R4130  *0_5%_2  [R0201]  183.41 81.25 270 bottom
R4131  *0_2  [R0201]  184.45 81.25 270 bottom
R4132  100K_1%_2  [R0201]  190.15 71.41 0 top
R4133  100K_1%_2  [R0201]  194.28 68.27 90 top
R4134  100K_1%_2  [R0201]  191.13 67.46 270 top
R4135  100K_1%_2  [R0201]  194.28 70.47 270 top
R4136  10K_5%_2  [R0201]  197.15 67.26 180 top
R4137  *0_2/S  [S0201]  182.67 84.12 0 top
R4139  *0_2/S  [S0201]  186.12 67.78 270 top
R4140  *10K_5%_2  [R0201]  187.74 71.36 90 top
R4141  100K_1%_2  [R0201]  179.7 81.25 90 bottom
R4144  *20K/F_2  [R0201]  180.69 82.34 180 bottom
R4151  *100K_1%_2  [R0201]  182.85 85.01 90 top
R4152  100K_1%_2  [R0201]  184.17 84.15 180 top
R4153  *0_2/S  [S0201]  174.42 81.13 180 bottom
R4154  *0_2/S  [S0201]  175.41 81.13 180 bottom
R4155  *0_5%_2/S  [S0201]  201.42 71.81 90 top
R4156  *0_5%_2/S  [S0201]  184.06 83.28 0 top
R4200  0.01_1%_6  [R0603]  198.91 3.71 270 top
R4201  *10K_5%_2  [R0201]  205.38 2.59 270 top
R4202  10K_5%_2  [R0201]  205.38 3.99 90 top
R4203  10K_5%_2  [R0201]  200.76 10.87 0 bottom
R4204  *0_2  [R0201]  207.41 10.06 270 top
R4205  *0_2/S  [S0201]  207.31 4.26 90 bottom
R4206  *0_2  [R0201]  196.8 10.89 180 bottom
R4207  *10K_5%_2  [R0201]  198.19 6.14 0 top
R4208  *100K_1%_2  [R0201]  194.74 6.8 180 top
R4209  *100K_1%_2  [R0201]  193.67 5.26 180 top
R4210  *0_2  [R0201]  191.91 3.86 270 top
R4211  *0_2/S  [S0201]  189.99 3.81 270 top
R4212  *0_2/S  [S0201]  191.46 11.63 90 bottom
R4213  *47K/F_2  [R0201]  186.71 7.16 180 top
R4214  *0_2  [R0201]  188.06 7.72 0 top
R4217  0_5%_2  [R0201]  196.92 5.38 180 top
R4218  0_5%_2  [R0201]  197.37 5.38 0 top
R4219  0_5%_2  [R0201]  213.18 10.31 180 top
R4220  *47K/F_2  [R0201]  214.75 9.4 180 top
R4221  0_5%_2  [R0201]  213.63 10.31 0 top
R4226  0_5%_2  [R0201]  204.95 6.37 0 top
R4227  0_5%_2  [R0201]  204.5 6.37 180 top
R4228  0_4  [R0402]  191.59 41.86 180 bottom
R4229  0_4  [R0402]  191.59 42.87 180 bottom
R4230  100K/F_2  [R0201]  208 5.26 180 top
R4231  *0_2  [R0201]  198.27 18.31 0 bottom
R4232  *0_2  [R0201]  198.27 19.02 0 bottom
R4233  *0_2  [R0201]  198.32 10.89 0 bottom
R4300  *0.01_1%_6/S  [S0603]  16.99 8.68 180 top
R4301  *0_4  [R0402]  11.8 5.07 180 top
R4304  *0_2/S  [S0201]  157.63 80.17 0 top
R4308  *10K/F_2  [R0201]  17.24 53.52 90 top
R4309  *0_2/S  [S0201]  18.26 54.23 180 top
R4311  *0_2  [R0201]  15.31 21.92 270 bottom
R4404  *0_2/S  [S0201]  211.07 11.07 90 top
R4405  *0_2  [R0201]  211.4 10.18 0 top
R4406  *0_2  [R0201]  205.23 1.72 180 top
R4407  470K_5%_2  [R0201]  176.17 86.97 270 top
R4408  *0_2/S  [S0201]  208.13 10.06 270 top
R4409  100K_5%_2  [R0201]  208.2 10.92 0 top
R4410  1M_1%_2  [R0201]  188.8 34.67 0 top
R4411  10K_5%_2  [R0201]  189.96 32.99 90 top
R4412  10K_5%_2  [R0201]  190.7 32.99 90 top
R4413  *0_2  [R0201]  145.84 52.25 180 top
R4414  *0_2/S  [S0201]  146.86 8.46 270 top
R4415  *0_2  [R0201]  147.6 8.46 90 top
R4416  *0_4/S  [S0402]  28.98 9.01 270 bottom
R4417  *0_4/S  [S0402]  28.01 9.01 270 bottom
R4701  33/F_2  [R0201]  201.83 23.15 90 top
R4702  33/F_2  [R0201]  199.16 24.92 90 top
R4703  33/F_2  [R0201]  198.37 24.97 90 top
R4704  33/F_2  [R0201]  201.52 25.12 90 top
R4705  33/F_2  [R0201]  201.83 24.14 90 top
R4706  33/F_2  [R0201]  200.78 24.94 90 top
R4707  4.7_5%_2  [R0201]  193.5 27.84 180 top
R4708  4.7_5%_2  [R0201]  190.96 26.46 90 top
R4709  4.7_5%_2  [R0201]  196.37 26.45 180 top
R4710  300_2  [R0201]  193.78 8.96 180 top
R4711  4.7_5%_2  [R0201]  192.89 26.62 180 top
R4712  300_2  [R0201]  194.43 14.73 270 bottom
R4714  300_2  [R0201]  195.17 14.65 270 bottom
R4717  300_2  [R0201]  191.29 9.68 180 top
R4718  10K_5%_2  [R0201]  189.43 11.76 180 top
R4719  10K_5%_2  [R0201]  191.59 11.76 270 top
R4720  *0_4/S  [S0402]  192.5 14.96 90 bottom
R4721  2.2K_2  [R0201]  188.01 25.22 90 top
R4722  2.2K_2  [R0201]  188.72 24.79 270 top
R4723  2.2K_2  [R0201]  202.03 17.65 270 bottom
R4724  2.2K_2  [R0201]  201.04 17.55 90 bottom
R4725  2.2/F_6  [R0603]  197.76 10.87 270 top
R4726  10K_5%_2  [R0201]  136.35 8.71 270 top
R4727  *1K_5%_2  [R0201]  138.53 9.83 0 bottom
R4728  *1K_5%_2  [R0201]  135.61 8.71 270 top
R4729  2.2/F_6  [R0603]  195.32 27.53 0 top
R4730  100K_1%_2  [R0201]  190.9 15.92 90 bottom
R4731  100K_1%_2  [R0201]  192.2 16.49 0 bottom
R4732  806K_1%_2  [R0201]  193.5 15.63 0 bottom
R4733  1K_1%_2  [R0201]  170.41 46.43 180 top
R4734  100K_1%_2  [R0201]  179.19 57.6 90 top
R4735  100K_1%_2  [R0201]  174.85 58.75 90 top
R4736  2.2/F_6  [R0603]  187.91 20.03 180 top
R4737  100K_1%_2  [R0201]  174.4 57.36 90 top
R4738  100K_1%_2  [R0201]  179.35 59.05 180 top
R4739  1K_1%_2  [R0201]  171.68 46.15 90 top
R4740  2.2/F_6  [R0603]  196.77 11.98 180 bottom
R4741  *100K_1%_2  [R0201]  199.08 25.91 90 top
R4742  *100K_1%_2  [R0201]  196.52 14.88 180 bottom
R4743  100K_2  [R0201]  171.09 44.17 90 top
R4744  100K_2  [R0201]  198.37 27.18 180 top
R4745  *0_2  [R0201]  180.03 57.71 90 top
R4746  *0_2  [R0201]  175.78 57.67 90 top
R4747  *0_2  [R0201]  202.31 13.56 0 top
R4748  100K_1%_2  [R0201]  76.38 95.22 180 top
R4749  *1K_5%_2  [R0201]  199.31 10.89 180 bottom
R4750  0_5%_2  [R0201]  24.21 7.51 270 top
R4751  0_5%_2  [R0201]  23.49 7.51 270 top
R4752  10K_1%_2  [R0201]  134.26 8.55 0 top
R4753  10K_1%_2  [R0201]  133.07 7.84 90 top
R4800  1M/F_2  [R0201]  191.74 18.16 180 bottom
R4802  100K_1%_2  [R0201]  157.19 38.53 90 top
R4803  470K_2  [R0201]  197.74 13.05 0 bottom
R4804  100K_1%_2  [R0201]  208.13 19.02 0 bottom
R4805  100K_1%_2  [R0201]  200.2 22.32 90 bottom
R4806  10K_5%_2  [R0201]  173.1 59.13 270 top
R4807  *10K_5%_2  [R0201]  188.82 22.22 90 top
R4808  *0_2/S  [S0201]  201.83 21.18 270 top
R4809  10K_5%_2  [R0201]  201.83 22.17 90 top
R4810  *1K_1%_2  [R0201]  200.18 11.76 270 top
R4811  20K/F_2  [R0201]  167.1 45.06 270 top
R4812  43_2  [R0201]  202.56 16.79 180 top
R4813  *10K_5%_2  [R0201]  207.03 19 180 bottom
R4814  *1K_1%_2  [R0201]  192.2 17.32 0 bottom
R4815  *1K_1%_2  [R0201]  187.91 21.96 270 top
R4816  100K_1%_2  [R0201]  167.71 35.56 0 top
R4817  100K_1%_2  [R0201]  166.85 35.94 90 top
R4818  43_2  [R0201]  167.71 36.98 180 top
R4819  *0_2  [R0201]  167.71 36.27 0 top
R4820  100K_1%_2  [R0201]  199.34 10.36 90 top
R4821  100K_2  [R0201]  179.58 3.05 270 top
R4822  10K_5%_2  [R0201]  188.92 23.82 0 top
R4823  34K_1%_2  [R0201]  193.32 11.73 90 top
R4824  34K_1%_2  [R0201]  194.1 11.73 270 top
R4825  10K_5%_2  [R0201]  184.94 9.62 270 top
R5000  200/F_4  [R0402]  133.37 10.72 90 top
R5002  200/F_4  [R0402]  129.82 9.8 0 top
R5004  200/F_4  [R0402]  128.09 9.09 180 top
R5005  *1M/F_2  [R0201]  177.57 61.54 90 top
R5007  470/F_4  [R0402]  128.09 10.06 0 top
R5009  470/F_4  [R0402]  127.68 11.45 0 top
R5010  *2M_2  [R0201]  177.8 63.78 90 top
R5011  200/F_4  [R0402]  125.52 10.74 270 top
R5013  *0_4/S  [S0402]  179.5 60.14 180 top
R5014  *0_2  [R0201]  123.52 10.59 270 top
R5015  *10K_10P8R_6  [10P8R]  118.61 8.39 180 top
R5016  *0_2/S  [S0201]  171.91 33.07 180 top
R5017  *20K/F_2  [R0201]  168.88 32.76 90 top
R5018  *0_2/S  [S0201]  172.51 34.59 270 top
R5019  *100K/F_2  [R0201]  171.27 34.59 270 top
R5026  100K_1%_2  [R0201]  44.48 9.7 180 bottom
R5027  1K_5%_2  [R0201]  30.33 24.71 180 bottom
R5028  200/F_4  [R0402]  135.51 10.41 0 bottom
R5100  150K/F_2  [R0201]  165.79 66.27 270 top
R5101  10K_5%_2  [R0201]  164.29 66.27 90 top
R5108  *10K_5%_2  [R0201]  162.84 67.33 180 top
R5110  *0_5%_2  [R0201]  165.02 66.27 90 top
R5111  *0_2/S  [S0201]  163.29 58.49 270 top
R5112  *0_2/S  [S0201]  167.71 60.78 90 top
R5120  *0_2/S  [S0201]  167.33 66.19 90 top
R5121  *0_2/S  [S0201]  160.58 60.45 270 top
R5122  4.7K_5%_2  [R0201]  164.79 58.21 90 top
R5123  *0_5%_2  [R0201]  165.56 58.11 270 top
R5124  *0_5%_2  [R0201]  164.06 57.5 270 top
R5125  *10K_5%_2  [R0201]  166.55 66.27 270 top
R5126  *4.7K_5%_2  [R0201]  165.36 57.09 90 top
R5127  *51K_2  [R0201]  169.75 64.34 90 top
R5128  *0_5%_2  [R0201]  164.06 58.49 90 top
R5129  *0_2/S  [S0201]  167.71 63.83 90 top
R5130  *10K_5%_2  [R0201]  168.6 64.59 180 top
R5200  *0_4/S  [S0402]  160.75 10.12 180 bottom
R5201  *0_4/S  [S0402]  160.75 11.13 180 bottom
R5202  100K_1%_2  [R0201]  157.55 11.35 270 bottom
R5203  330T30_4  [R0402]  36 6.47 0 top
R5204  330T30_4  [R0402]  37.72 6.47 180 top
R5208  *0_4/S  [S0402]  40.79 6.86 270 top
R5211  *0_4/S  [S0402]  39.44 6.47 180 top
R5212  10K/F_2  [R0201]  40.89 7.34 180 bottom
R5214  *Short_0201  [S0201]  41.22 12.01 90 top
R5215  *Short_0201  [S0201]  41.98 12.01 90 top
R5216  *0.01_1%_6/S  [S0603]  41.6 11.5 180 top
R5217  *1M/F_2  [R0201]  27.58 7.28 270 top
R5218  100K_1%_2  [R0201]  35.35 7.95 180 top
R5400  *0.01_1%_4/S  [S0402]  27.17 65.6 0 top
R5401  4.7K_5%_2  [R0201]  33.09 56.89 90 bottom
R5402  22/F_2  [R0201]  33.12 57.76 180 bottom
R5403  10K_5%_2  [R0201]  34.31 59.05 0 bottom
R5404  1.2K_5%_2  [R0201]  32.36 58.75 180 bottom
R5405  150/F_4  [R0402]  31.98 76.65 90 bottom
R5406  *470K_2  [R0201]  31.9 75.44 180 bottom
R5407  10K/F_2  [R0201]  91.77 81.23 0 bottom
R5408  33.2K/F_4  [R0402]  32.21 72.24 180 bottom
R5417  2.2K_2  [R0201]  88.67 70.13 270 bottom
R5418  2.2K_2  [R0201]  92.55 71.3 90 bottom
R5419  *0_5%_2/S  [S0201]  154.28 18.01 180 bottom
R5601  22/F_2  [R0201]  164.16 73.3 90 top
R5602  22/F_2  [R0201]  163.45 73.3 270 top
R5603  22/F_2  [R0201]  159.54 74.88 270 top
R5604  22/F_2  [R0201]  159.03 73.67 270 top
R5605  22/F_2  [R0201]  166.49 70.81 180 bottom
R5606  22/F_2  [R0201]  165.43 72.16 180 bottom
R5607  15_2  [R0201]  151.66 68.15 270 top
R5608  15_2  [R0201]  159.22 92.07 90 top
R5612  22/F_2  [R0201]  167.51 70.61 180 bottom
R5613  22/F_2  [R0201]  166.49 71.52 180 bottom
R5622  *0.01_1%_6/S  [S0603]  170.61 93.8 0 top
R5623  4.7K_5%_2  [R0201]  168.35 96.04 180 top
R5624  *2.55K/F_2  [R0201]  160.2 93.16 90 top
R5625  *3.3K/F_2  [R0201]  159.18 93.23 270 top
R5626  *3.3K/F_2  [R0201]  163.65 89.38 180 top
R5627  *0_4  [R0402]  165.43 88.21 90 top
R5628  *0_4/S  [S0402]  190.12 26.79 90 top
R5629  4.7K/F_2  [R0201]  200.2 29.51 180 bottom
R5630  33/F_2  [R0201]  202.16 25.75 90 bottom
R5631  *3.3K_1%_2  [R0201]  191.18 28.01 180 top
R5632  3.3K_1%_2  [R0201]  198.37 27.97 180 top
R5633  33/F_2  [R0201]  200.35 27.68 180 top
R5634  33/F_2  [R0201]  191.26 29.31 0 top
R5635  *1K_1%_2  [R0201]  162.13 76.1 270 top
R5636  1.5K_5%_2  [R0201]  163.6 76.27 180 top
R5637  1K_1%_2  [R0201]  163.9 71.78 0 top
R5900  2.2_5%_2  [R0201]  192.47 100.88 0 bottom
R5901  *0.01_1%_4/S  [S0402]  186.64 57.96 90 bottom
R5902  2.2_5%_2  [R0201]  192.47 99.74 0 bottom
R5903  2.2_5%_2  [R0201]  191.38 98.9 0 bottom
R5904  2.2_5%_2  [R0201]  191.38 97.75 0 bottom
R5905  2.2_5%_2  [R0201]  191.38 93.66 0 bottom
R5906  2.2_5%_2  [R0201]  191.38 92.52 0 bottom
R5907  2.2_5%_2  [R0201]  191.38 95.83 0 bottom
R5908  2.2_5%_2  [R0201]  191.38 94.69 0 bottom
R5909  0_4  [R0402]  191.36 103.36 90 bottom
R5910  0_4  [R0402]  192.34 103.35 90 bottom
R5911  0_5%_2  [R0201]  197.38 96.87 270 bottom
R5912  0_5%_2  [R0201]  196.26 96.87 270 bottom
R5913  *1M_1%_2  [R0201]  192.34 102.08 0 bottom
R5914  *1M_1%_2  [R0201]  191.27 102.07 180 bottom
R5915  *1M_1%_2  [R0201]  185.61 103.59 0 bottom
R5916  0_5%_2  [R0201]  185.57 91.29 270 bottom
R5917  *1M_1%_2  [R0201]  184.31 101.97 180 bottom
R5918  0_5%_2  [R0201]  184.83 91.29 270 bottom
R5919  0_5%_2  [R0201]  187.51 94.71 90 top
R5920  100K_2  [R0201]  189.01 94.27 180 top
R5921  0_5%_2  [R0201]  186.29 93.77 270 top
R5922  100_1%_2  [R0201]  181.36 93.62 90 bottom
R5923  0_5%_2  [R0201]  189.25 91.29 270 bottom
R5924  10K_1%_2  [R0201]  188.51 91.31 270 bottom
R5925  10K_1%_2  [R0201]  186.31 91.29 90 bottom
R5926  *10K_1%_2  [R0201]  187.04 91.29 90 bottom
R5927  *0_5%_2  [R0201]  189.75 95.29 270 top
R5928  0_5%_2  [R0201]  189.52 96.19 180 top
R5929  *10K_1%_2  [R0201]  190.69 91.5 270 bottom
R5930  10K_1%_2  [R0201]  189.97 91.51 270 bottom
R5931  4.75K_0.5%_4  [R0402]  182.42 99.26 180 top
R5932  10K_1%_2  [R0201]  181.4 91.29 270 bottom
R5933  10K_1%_2  [R0201]  183.4 91.29 270 bottom
R5934  *10K_1%_2  [R0201]  182.95 89.83 90 bottom
R5935  *10K_1%_2  [R0201]  183.68 89.83 270 bottom
R5936  0_5%_4  [R0402]  185.4 99.3 180 top
R5937  10K_1%_2  [R0201]  179.86 91.29 270 bottom
R5938  10K_1%_2  [R0201]  187.77 91.29 90 bottom
R5939  10K_1%_2  [R0201]  180.62 91.29 270 bottom
R5940  3.32K_1%_2  [R0201]  188.46 58.38 270 bottom
R5941  10K_1%_2  [R0201]  182.67 91.29 270 bottom
R5942  2.2K_5%_2  [R0201]  178.05 61.31 180 bottom
R5943  10K_1%_2  [R0201]  184.43 89.84 270 bottom
R5944  2.2K_5%_2  [R0201]  178.05 62.46 180 bottom
R5945  3.32K_1%_2  [R0201]  178.56 63.65 180 bottom
R5947  0_5%_2  [R0201]  176.57 98.62 0 top
R5948  10K_5%_2  [R0201]  172.44 105.26 270 top
R5949  0_5%_2  [R0201]  191.83 98.9 180 bottom
R5950  0_5%_2  [R0201]  176.57 99.76 0 top
R5951  0_5%_2  [R0201]  191.83 97.75 180 bottom
R5952  0_5%_2  [R0201]  176.18 96.21 0 top
R5953  0_5%_2  [R0201]  192.92 100.88 180 bottom
R5954  0_5%_2  [R0201]  176.18 97.35 0 top
R5955  0_5%_2  [R0201]  192.92 99.74 180 bottom
R5956  0_5%_2  [R0201]  176.57 91.63 0 top
R5957  0_5%_2  [R0201]  191.83 95.83 180 bottom
R5958  0_5%_2  [R0201]  176.57 92.78 0 top
R5959  0_5%_2  [R0201]  191.83 94.69 180 bottom
R5960  0_5%_2  [R0201]  176.57 94.05 0 top
R5961  0_5%_2  [R0201]  191.83 93.66 180 bottom
R5962  0_5%_2  [R0201]  176.57 95.19 0 top
R5963  0_5%_2  [R0201]  191.83 92.52 180 bottom
R5964  33_5%_2  [R0201]  188.96 101.2 90 bottom
R5965  33_5%_2  [R0201]  188.17 101.2 90 bottom
R6100  *4.7K_2  [R0201]  195.96 87.27 180 bottom
R6101  10K/F_2  [R0201]  192.73 80.67 270 bottom
R6102  *0_2/S  [S0201]  194.49 90.35 180 bottom
R6103  *0_4/S  [S0402]  191.34 89.81 0 bottom
R6104  0.005_1%_6  [R0603]  193.67 90.17 180 top
R6105  *4.7K_2  [R0201]  195.96 86.56 0 bottom
R6106  4.7K_5%_2  [R0201]  191.97 80.67 90 bottom
R6107  2.2K_5%_2  [R0201]  164.9 84.96 270 top
R6108  2.2K_5%_2  [R0201]  165.98 84.98 270 top
R6109  2.2K_5%_2  [R0201]  186.71 82.37 180 bottom
R6110  100K/F_4  [R0402]  196.49 80.46 0 bottom
R6112  300K_1%_4  [R0402]  196.49 81.48 180 bottom
R6114  2.2K_5%_2  [R0201]  193.5 80.67 90 bottom
R6115  *0_2  [R0201]  192.3 69.62 0 bottom
R6117  100K_1%_2  [R0201]  196.26 96.42 90 top
R6119  100K_1%_2  [R0201]  197.33 96.42 90 top
R6122  0_2  [R0201]  195.65 91.49 0 bottom
R6123  0_2  [R0201]  195.65 92.2 0 bottom
R6124  100K_5%_2  [R0201]  194.7 94.75 90 bottom
R6125  0_2  [R0201]  194.49 93.22 270 bottom
R6127  *Short_0201  [S0201]  193.09 90.7 90 top
R6128  *Short_0201  [S0201]  194.56 90.7 90 top
R6129  *0_2  [R0201]  186.71 81.66 0 bottom
R6200  22K_1%_2  [R0201]  194.77 82.6 270 top
R6201  39K/F_4  [R0402]  194.26 83.59 0 top
R6202  *0_2  [R0201]  199.44 80.13 90 top
R6203  10K/F_2  [R0201]  200.73 83.2 270 top
R6304  220K_5%_2  [R0201]  209.35 112.59 90 top
R6305  220K_5%_2  [R0201]  209.34 111.58 270 top
R6306  220K_5%_2  [R0201]  208.14 106.34 90 top
R6307  220K_5%_2  [R0201]  208.15 105.31 270 top
R6308  220K_5%_2  [R0201]  208.55 109.95 90 top
R6309  220K_5%_2  [R0201]  208.55 108.93 270 top
R6310  220K_5%_2  [R0201]  208.56 103.35 90 top
R6311  220K_5%_2  [R0201]  208.56 102.33 270 top
R6314  *2M_2  [R0201]  208.72 107.23 0 bottom
R6319  *2M_2  [R0201]  210.11 110.97 180 bottom
R6602  10K/F_2  [R0201]  81.76 60.27 270 bottom
R6611  100K/F_2  [R0201]  78.94 58.04 270 bottom
R6612  *200/F_4  [R0402]  68.6 62.81 270 bottom
R6615  4.7K_5%_2  [R0201]  80.43 63.28 180 bottom
R6616  10K/F_2  [R0201]  69.95 63.27 0 bottom
R6617  2.49K_1%_2  [R0201]  67.59 62.56 90 bottom
R6618  10K/4  [R0402]  84.53 69.67 90 top
R6619  2.21K_1%_4  [R0402]  83.13 69.03 0 top
R6701  10K/F_2  [R0201]  53.67 84.15 0 bottom
R6702  10K/F_2  [R0201]  53.67 81.23 180 bottom
R6703  10K/F_2  [R0201]  53.67 83.26 0 bottom
R6704  10K/F_2  [R0201]  51.16 80.67 270 top
R6705  40.2_1%_4  [R0402]  54.81 92.2 90 top
R6706  40.2_1%_4  [R0402]  57.35 91.74 90 bottom
R6707  40.2_1%_4  [R0402]  56.39 91.74 90 bottom
R6708  *60.4_2  [R0201]  61.69 84.5 180 top
R6709  *60.4_2  [R0201]  62.46 81.33 180 top
R6710  *0_2  [R0201]  83.45 99.2 0 bottom
R6712  100K/F_2  [R0201]  86.6 99.07 180 bottom
R6713  49.9_1%_2  [R0201]  53.8 91.01 180 top
R6800  10K_5%_2  [R0201]  79.73 93.07 0 bottom
R6804  *10K/F_2  [R0201]  70.56 93.29 90 top
R6805  10K/F_2  [R0201]  75.46 92.45 90 bottom
R6806  10K/F_2  [R0201]  70.69 92.28 0 top
R6807  *4.7K_2  [R0201]  75.49 94.69 0 bottom
R6808  4.7K_5%_2  [R0201]  48.61 57.66 90 bottom
R6809  4.7K_5%_2  [R0201]  61.36 93.55 90 bottom
R6810  100K/F_2  [R0201]  75.49 95.4 0 bottom
R6811  *4.7K_2  [R0201]  37.51 59.51 90 bottom
R6812  *0_2/S  [S0201]  43.36 57.1 90 bottom
R6826  10K_5%_2  [R0201]  57.15 98.91 180 top
R6828  33.2_1%_2  [R0201]  65.35 93.93 180 top
R6831  33.2_1%_2  [R0201]  54.53 96.97 270 top
R6838  33.2_1%_2  [R0201]  65.35 95.83 0 top
R6839  10K_5%_2  [R0201]  57.35 92.66 180 top
R6841  10K_5%_2  [R0201]  65.1 97.36 270 top
R6902  *100K_5%_4  [R0402]  69.2 94.07 270 bottom
R6903  *100K_5%_4  [R0402]  68.05 94.07 270 bottom
R6904  *100K_5%_4  [R0402]  70.21 94.07 270 bottom
R6905  *100K_4  [R0402]  84.43 77.9 180 bottom
R6906  *100K_4  [R0402]  84.43 78.89 180 bottom
R6907  100K_4  [R0402]  84.43 76.88 180 bottom
R6908  *100K_4  [R0402]  84.43 75.77 180 bottom
R6909  *100K_4  [R0402]  84.43 81.13 180 bottom
R6910  *100K_4  [R0402]  84.43 80.11 180 bottom
R6911  100K_5%_4  [R0402]  69.19 92.28 270 bottom
R6912  10K/4  [R0402]  68.04 92.28 270 bottom
R6913  100K_5%_4  [R0402]  70.2 92.28 270 bottom
R6914  100K_4  [R0402]  82.65 77.9 180 bottom
R6915  100K_4  [R0402]  82.65 78.89 180 bottom
R6916  *100K_4  [R0402]  82.65 76.88 180 bottom
R6917  100K_4  [R0402]  82.65 75.77 180 bottom
R6918  100K_4  [R0402]  82.65 81.13 180 bottom
R6919  100K_4  [R0402]  82.65 80.11 180 bottom
R6923  4.7K_5%_2  [R0201]  76.82 92.94 180 bottom
R6924  1.8K_5%_2  [R0201]  72.21 92.89 90 top
R6926  1.8K_5%_2  [R0201]  72.97 92.89 90 top
R6927  4.7K_5%_2  [R0201]  77.77 92.78 270 bottom
R6928  1.8K_5%_2  [R0201]  75.11 95.37 180 top
R6929  1.8K_5%_2  [R0201]  75.11 94.64 180 top
R6943  10K_5%_2  [R0201]  86.59 71.47 270 bottom
R6944  *0_4  [R0402]  83.81 59.97 270 bottom
R6946  4.7K_5%_2  [R0201]  85.55 63.68 270 bottom
R6947  10K_5%_2  [R0201]  84.22 68.82 0 bottom
R6950  100K/F_2  [R0201]  75.11 96.11 0 top
R6951  10K/F_2  [R0201]  85.06 88.62 0 bottom
R6952  10K/F_2  [R0201]  79.86 91.5 90 bottom
R6953  10K/F_2  [R0201]  82.9 79.83 0 top
R6954  10K_5%_2  [R0201]  85.65 60.27 270 bottom
R6956  10K/F_2  [R0201]  85.06 87.81 0 bottom
R6957  *10K_2  [R0201]  86.05 80.21 180 bottom
R6958  10K/F_2  [R0201]  84.91 86.59 270 bottom
R6960  75K_1%_2  [R0201]  82.4 85.67 270 bottom
R6961  *12.1K/F_2  [R0201]  83.28 85.19 90 bottom
R6962  10K/F_2  [R0201]  79.9 99.19 90 top
R6963  10K/F_2  [R0201]  83.51 66.67 180 bottom
R6964  100K/F_2  [R0201]  79.5 100.07 180 top
R6965  *0_5%_6/S  [S0603]  68.86 93.5 0 top
R7000  549/F_2  [R0201]  32 93.85 180 top
R7001  931/F_2  [R0201]  31.06 95.81 180 top
R7002  1.33K/F_2  [R0201]  30.12 94.1 0 top
R7003  120/F_2  [R0201]  32.36 85.21 0 bottom
R7004  1K/F_2  [R0201]  38.71 88.44 270 top
R7005  120/F_2  [R0201]  32.59 70.58 0 bottom
R7006  1K/F_2  [R0201]  37.97 70.05 90 top
R7007  1K/F_2  [R0201]  49.22 88.5 180 bottom
R7008  40.2_1%_4  [R0402]  35.76 71.09 0 top
R7009  *1K/F_2  [R0201]  49.22 71.45 180 bottom
R7010  40.2_1%_4  [R0402]  35.76 70.13 0 top
R7011  549/F_2  [R0201]  33.09 75.99 180 bottom
R7012  931/F_2  [R0201]  32.59 71.35 180 bottom
R7013  1K/F_2  [R0201]  49.22 70.5 180 bottom
R7014  40.2_1%_4  [R0402]  36.14 88.95 0 top
R7015  40.2_1%_4  [R0402]  36.14 87.98 0 top
R7016  1.33K/F_2  [R0201]  31.95 74.55 90 bottom
R7017  *1.33K/F_4  [R0402]  30.02 92.89 270 top
R7018  *1.33K/F_4  [R0402]  32.89 74.78 270 bottom
R7500  470K_2  [R0201]  23.32 40.74 0 top
R7501  *0_4  [R0402]  23.04 38.99 0 top
R7502  2.2K_2  [R0201]  23.49 41.6 90 top
R7503  *10K/F_2  [R0201]  20.64 41.53 270 top
R7504  *0_4/S  [S0402]  21.51 39.95 270 top
R7505  *0_4/S  [S0402]  21.41 44.63 270 top
R7506  *0_4/S  [S0402]  22.55 44.4 90 top
R7507  100K_2  [R0201]  22.38 40.31 270 top
